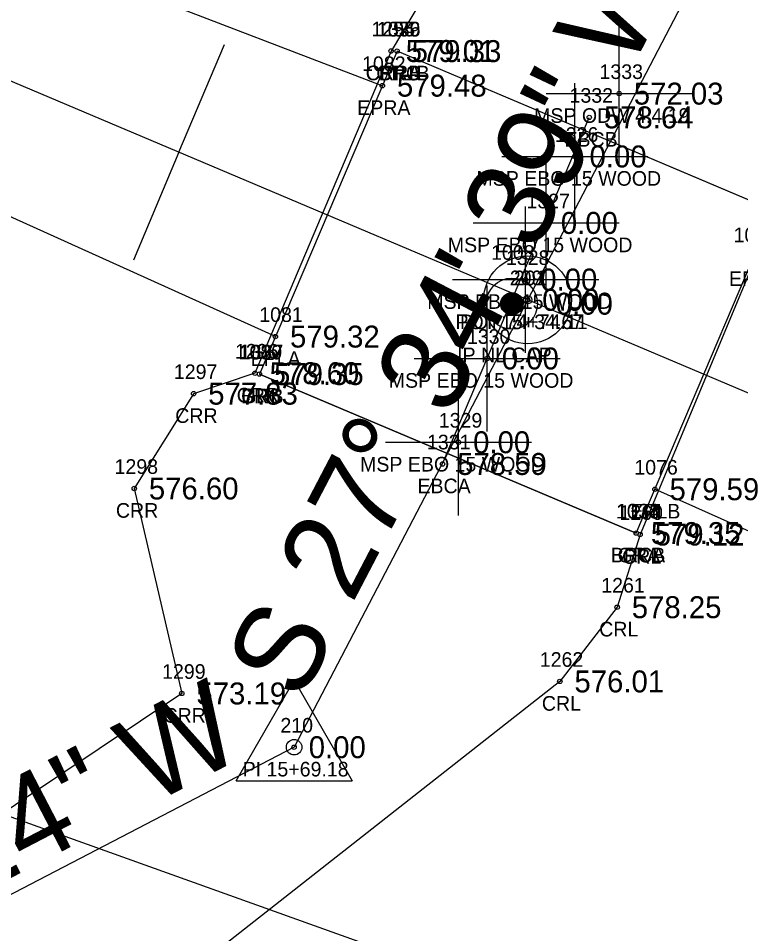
# Model space of a CAD drawing. Extents: x 1664393 to 1667175, y 987029 to 988607.
# Drawn here: x 1665481.2 to 1665530.6, y 987718.5 to 987781.1 of the extents above; entities that cross this region are included whole.
import ezdxf

# ---------------------------------------------------------------- set-up
doc = ezdxf.new("R2010")
doc.units = 0
for name, color, linetype in [('RD_EX_Bridge', 7, 'Continuous'), ('RD_EX_Bridge_txCode', 7, 'Continuous'), ('RD_EX_DV_Prop_txCode', 7, 'Continuous'), ('RD_EX_DV_PropPin', 7, 'Continuous'), ('RD_EX_GuardRail', 7, 'Continuous'), ('RD_EX_GuardRail_txCode', 7, 'Continuous'), ('RD_EX_H2O', 7, 'Continuous'), ('RD_EX_H2O_txCode', 7, 'Continuous'), ('RD_EX_Road', 7, 'Continuous'), ('RD_EX_Road_txCode', 7, 'Continuous'), ('RD_EX_TX_Bridge_ELEV', 7, 'Continuous'), ('RD_EX_TX_DV_Prop_ELEV', 7, 'Continuous'), ('RD_EX_TX_GuardRail_ELEV', 7, 'Continuous'), ('RD_EX_TX_H2O_ELEV', 7, 'Continuous'), ('RD_EX_TX_Misc_ELEV', 7, 'Continuous'), ('RD_EX_TX_Road_ELEV', 7, 'Continuous'), ('RD_EX_VEG', 7, 'Continuous'), ('RD_HC_Cl', 7, 'Continuous'), ('RD_HC_Data', 7, 'Continuous'), ('RD_HC_Data_Tic', 7, 'Continuous'), ('RD_HC_Survey_ELEV', 7, 'Continuous'), ('RD_HC_txCode', 7, 'Continuous'), ('RD_SMD_Locator', 7, 'Continuous')]:
    doc.layers.add(name, color=color, linetype=linetype)

msp = doc.modelspace()

# ---------------------------------------------------------------- linework, layer by layer
at = {"layer": 'RD_EX_Bridge'}
for p, q in [((1665519.233, 987766.682), (1665519.233, 987776.682)), ((1665510.179, 987750.658), (1665520.213, 987774.354)), ((1665517.271, 987762.137), (1665517.271, 987772.137)), ((1665514.233, 987771.682), (1665524.233, 987771.682)), ((1665515.864, 987758.264), (1665515.864, 987768.264)), ((1665512.271, 987767.137), (1665522.271, 987767.137)), ((1665510.864, 987763.264), (1665520.864, 987763.264)), ((1665513.234, 987752.871), (1665513.234, 987762.871)), ((1665508.234, 987757.871), (1665518.234, 987757.871)), ((1665511.271, 987747.143), (1665511.271, 987757.143)), ((1665506.271, 987752.143), (1665516.271, 987752.143))]:
    msp.add_line(p, q, dxfattribs=at)
msp.add_lwpolyline([(1665523.429, 987745.932), (1665532.82, 987767.978), (1665507.067, 987778.884), (1665497.653, 987756.806), (1665523.429, 987745.932)], dxfattribs=at)
for centre in [(1665519.233, 987771.682), (1665517.271, 987767.137), (1665515.864, 987763.264), (1665513.234, 987757.871), (1665511.271, 987752.143)]:
    msp.add_circle(centre, 0.15, dxfattribs=at)
at = {"layer": 'RD_EX_DV_PropPin'}
for p, q in [((1665514.292, 987761.19), (1665514.292, 987762.043)), ((1665514.327, 987761.142), (1665514.327, 987762.09)), ((1665514.362, 987761.101), (1665514.362, 987762.131)), ((1665514.397, 987761.065), (1665514.397, 987762.167)), ((1665514.432, 987761.034), (1665514.432, 987762.198)), ((1665514.467, 987761.006), (1665514.467, 987762.226)), ((1665514.502, 987760.982), (1665514.502, 987762.251)), ((1665514.537, 987760.96), (1665514.537, 987762.273)), ((1665514.572, 987760.941), (1665514.572, 987762.292)), ((1665514.607, 987760.923), (1665514.607, 987762.309)), ((1665514.642, 987760.909), (1665514.642, 987762.324)), ((1665514.677, 987760.896), (1665514.677, 987762.337)), ((1665514.712, 987760.885), (1665514.712, 987762.348)), ((1665514.748, 987760.876), (1665514.748, 987762.357)), ((1665514.783, 987760.868), (1665514.783, 987762.364)), ((1665514.818, 987760.862), (1665514.818, 987762.37)), ((1665514.853, 987760.858), (1665514.853, 987762.374)), ((1665514.888, 987760.856), (1665514.888, 987762.376)), ((1665514.923, 987760.855), (1665514.923, 987762.377)), ((1665514.958, 987760.856), (1665514.958, 987762.376)), ((1665514.993, 987760.858), (1665514.993, 987762.374)), ((1665515.028, 987760.862), (1665515.028, 987762.37)), ((1665515.063, 987760.868), (1665515.063, 987762.364)), ((1665515.098, 987760.876), (1665515.098, 987762.357)), ((1665515.133, 987760.885), (1665515.133, 987762.348)), ((1665515.168, 987760.896), (1665515.168, 987762.337)), ((1665515.203, 987760.909), (1665515.203, 987762.324)), ((1665515.238, 987760.923), (1665515.238, 987762.309)), ((1665515.273, 987760.941), (1665515.273, 987762.292)), ((1665515.308, 987760.96), (1665515.308, 987762.273)), ((1665515.343, 987760.982), (1665515.343, 987762.251)), ((1665515.378, 987761.006), (1665515.378, 987762.226)), ((1665515.413, 987761.034), (1665515.413, 987762.198)), ((1665515.448, 987761.065), (1665515.448, 987762.167)), ((1665515.483, 987761.101), (1665515.483, 987762.131)), ((1665515.518, 987761.142), (1665515.518, 987762.09)), ((1665515.553, 987761.19), (1665515.553, 987762.043)), ((1665514.187, 987761.42), (1665514.187, 987761.812)), ((1665514.222, 987761.318), (1665514.222, 987761.914)), ((1665514.257, 987761.247), (1665514.257, 987761.986)), ((1665515.588, 987761.247), (1665515.588, 987761.986)), ((1665515.623, 987761.318), (1665515.623, 987761.914)), ((1665515.658, 987761.42), (1665515.658, 987761.812))]:
    msp.add_line(p, q, dxfattribs=at)
for radius in [1.75, 0.761]:
    msp.add_circle((1665514.923, 987761.616), radius, dxfattribs=at)
at = {"layer": 'RD_EX_GuardRail'}
for p, q in [((1665532.82, 987767.978), (1665507.067, 987778.884)), ((1665523.429, 987745.932), (1665497.653, 987756.806))]:
    msp.add_line(p, q, dxfattribs=at)
at = {"layer": 'RD_EX_H2O'}
for p, q in [((1665510.35, 987785.057), (1665506.659, 987778.891)), ((1665522.262, 987770.978), (1665522.262, 987780.978)), ((1665517.262, 987775.978), (1665527.262, 987775.978))]:
    msp.add_line(p, q, dxfattribs=at)
for points in [[(1665565.694, 987792.782), (1665555.482, 987787.59), (1665542.576, 987772.172), (1665532.862, 987767.806), (1665532.862, 987767.806), (1665523.69, 987745.834), (1665522.123, 987740.867), (1665518.202, 987735.792), (1665482.823, 987707.998), (1665483.869, 987700.867), (1665513.494, 987706.089), (1665528.039, 987685.521), (1665561.972, 987665.976), (1665593.475, 987679.218), (1665619.367, 987685.12), (1665642.781, 987680.312), (1665663.972, 987651.849), (1665686.025, 987634.258), (1665705.625, 987627.984), (1665724.83, 987594.973)], [(1665506.659, 987778.891), (1665497.349, 987756.863), (1665493.147, 987755.465), (1665489.09, 987748.984), (1665492.342, 987734.97), (1665472.457, 987721.678), (1665444.705, 987712.07), (1665426.388, 987705.523), (1665387.142, 987692.073), (1665353.811, 987678.169), (1665328.18, 987659.888), (1665283.875, 987652.208), (1665224.392, 987676.289), (1665206.474, 987666.979), (1665167.328, 987633.903), (1665123.228, 987629.541), (1665093.052, 987625.537), (1665046.907, 987607.08)]]:
    msp.add_lwpolyline(points, dxfattribs=at)
msp.add_circle((1665522.262, 987775.978), 0.15, dxfattribs=at)
at = {"layer": 'RD_EX_Road'}
for points in [[(1665506.06, 987776.522), (1665471.951, 987789.573), (1665426.522, 987809.188), (1665380.334, 987828.776), (1665335.608, 987847.528), (1665288.25, 987866.825), (1665242.335, 987886.564), (1665197.072, 987906.161), (1665152.201, 987925.426), (1665127.55, 987936.697), (1665104.502, 987945.201), (1665059.192, 987965.303), (1665013.627, 987984.661), (1664966.375, 988005.065), (1664921.664, 988023.835), (1664875.548, 988043.801)], [(1665498.746, 987759.368), (1665465.875, 987774.203), (1665419.779, 987793.882), (1665373.623, 987813.14), (1665327.947, 987832.311), (1665281.425, 987852.296), (1665236.128, 987871.343), (1665189.603, 987890.715), (1665143.921, 987909.971), (1665117.427, 987920.989), (1665086.217, 987934.267), (1665051.623, 987948.552), (1665005.385, 987968.44), (1664960.172, 987987.671), (1664913.527, 988007.622), (1664868.206, 988026.815)], [(1666156.674, 987480.61), (1666109.284, 987500.741), (1666063.55, 987520.043), (1666017.041, 987539.822), (1665971.114, 987559.142), (1665924.884, 987578.792), (1665879.498, 987597.891), (1665833.217, 987617.382), (1665786.906, 987636.812), (1665741.438, 987656.129), (1665695.815, 987675.204), (1665649.264, 987694.848), (1665603.559, 987714.712), (1665558.4, 987733.869), (1665524.706, 987748.932)]]:
    msp.add_lwpolyline(points, dxfattribs=at)
at = {"layer": 'RD_EX_VEG'}
msp.add_lwpolyline([(1666150.204, 987465.221), (1665963.159, 987547.122), (1665727.121, 987646.514), (1665543.179, 987704.13), (1665449.914, 987737.525), (1665163.848, 987870.347), (1665156.075, 987854.029)], dxfattribs=at)
at = {"layer": 'RD_HC_Cl'}
for p, q in [((1666160.052, 987489.414), (1664963.07, 987995.795)), ((1665529.145, 987787.051), (1665500.025, 987731.295)), ((1665500.025, 987731.295), (1665445.607, 987702.995))]:
    msp.add_line(p, q, dxfattribs=at)
at = {"layer": 'RD_HC_Data'}
for p, q in [((1665496.054, 987729.002), (1665500.026, 987735.882)), ((1665500.026, 987735.882), (1665503.995, 987729.002)), ((1665496.054, 987729.002), (1665503.995, 987729.002))]:
    msp.add_line(p, q, dxfattribs=at)
for centre, radius in [((1665515.999, 987761.879), 3), ((1665515.999, 987761.879), 3), ((1665515.999, 987761.879), 0.282), ((1665515.999, 987761.879), 0.282), ((1665500.025, 987731.295), 0.529)]:
    msp.add_circle(centre, radius, dxfattribs=at)
at = {"layer": 'RD_HC_Data_Tic'}
for q in [(1665495.267, 987779.336), (1665489.033, 987764.6)]:
    msp.add_line((1665492.15, 987771.968), q, dxfattribs=at)
at = {"layer": 'RD_SMD_Locator'}
for centre in [(1665506.659, 987778.891), (1665506.659, 987778.891), (1665507.067, 987778.884), (1665507.067, 987778.884), (1665506.06, 987776.522), (1665520.213, 987774.354), (1665515.999, 987761.879), (1665515.999, 987761.879), (1665514.923, 987761.616), (1665498.746, 987759.368), (1665497.349, 987756.863), (1665497.653, 987756.806), (1665497.653, 987756.806), (1665493.147, 987755.465), (1665510.179, 987750.658), (1665489.09, 987748.984), (1665524.706, 987748.932), (1665523.429, 987745.932), (1665523.429, 987745.932), (1665523.429, 987745.932), (1665523.69, 987745.834), (1665522.123, 987740.867), (1665518.202, 987735.792), (1665492.342, 987734.97), (1665500.025, 987731.295)]:
    msp.add_circle(centre, 0.15, dxfattribs=at)

# ---------------------------------------------------------------- texts
at = {"layer": 'RD_EX_Bridge_txCode'}
for s, p in [('1336', (1665505.697, 987779.884)), ('BRC', (1665505.815, 987776.884)), ('1332', (1665518.867, 987775.354)), ('1326', (1665517.863, 987772.682)), ('EBCB', (1665518.513, 987772.354)), ('MSP EBO 15 WOOD', (1665512.5, 987769.682)), ('1327', (1665515.924, 987768.137)), ('MSP EBO 15 WOOD', (1665510.539, 987765.137)), ('1328', (1665514.518, 987764.264)), ('MSP EBO 15 WOOD', (1665509.132, 987761.264)), ('1330', (1665511.848, 987758.871)), ('1337', (1665496.307, 987757.806)), ('MSP EBO 15 WOOD', (1665506.501, 987755.871)), ('BRC', (1665496.401, 987754.806)), ('1329', (1665509.924, 987753.143)), ('1331', (1665509.116, 987751.658)), ('MSP EBO 15 WOOD', (1665504.538, 987750.143)), ('EBCA', (1665508.462, 987748.658)), ('1334', (1665522.082, 987746.932)), ('1338', (1665522.082, 987746.932)), ('BRCA', (1665521.688, 987743.932)), ('BRCB', (1665521.704, 987743.932))]:
    msp.add_text(s, height=1, dxfattribs=at).set_placement(p)
at = {"layer": 'RD_EX_DV_Prop_txCode'}
for s, p in [('1008', (1665513.497, 987764.616)), ('IP NL CAP', (1665511.175, 987757.616))]:
    msp.add_text(s, height=1, dxfattribs=at).set_placement(p)
at = {"layer": 'RD_EX_GuardRail_txCode'}
for s, p in [('1079', (1665505.681, 987779.884)), ('GR1B', (1665505.65, 987776.884)), ('1080', (1665496.228, 987757.806)), ('GRB', (1665496.401, 987754.806)), ('1077', (1665522.043, 987746.932)), ('GRA', (1665522.161, 987743.932))]:
    msp.add_text(s, height=1, dxfattribs=at).set_placement(p)
at = {"layer": 'RD_EX_H2O_txCode'}
for s, p in [('1254', (1665505.313, 987779.891)), ('1295', (1665505.313, 987779.891)), ('CRRA', (1665504.919, 987776.891)), ('CRRB', (1665504.935, 987776.891)), ('1333', (1665520.916, 987776.978)), ('MSP ODW 4.4.19', (1665516.443, 987773.978)), ('1296', (1665495.979, 987757.863)), ('1297', (1665491.801, 987756.465)), ('CRR', (1665496.097, 987754.863)), ('CRR', (1665491.895, 987753.465)), ('1298', (1665487.744, 987749.984)), ('CRR', (1665487.838, 987746.984)), ('1260', (1665522.28, 987746.834)), ('CRL', (1665522.461, 987743.834)), ('1261', (1665521.037, 987741.867)), ('CRL', (1665520.895, 987738.867)), ('1262', (1665516.832, 987736.792)), ('1299', (1665490.996, 987735.97)), ('CRL', (1665516.974, 987733.792)), ('CRR', (1665491.09, 987732.97))]:
    msp.add_text(s, height=1, dxfattribs=at).set_placement(p)
at = {"layer": 'RD_EX_Road_txCode'}
for s, p in [('1082', (1665504.674, 987777.522)), ('EPRA', (1665504.343, 987774.522)), ('1075', (1665530.089, 987765.82)), ('EPRB', (1665529.774, 987762.82)), ('1081', (1665497.643, 987760.368)), ('EPLA', (1665497.053, 987757.368)), ('1076', (1665523.297, 987749.932)), ('EPLB', (1665523.029, 987746.932))]:
    msp.add_text(s, height=1, dxfattribs=at).set_placement(p)
at = {"layer": 'RD_EX_TX_Bridge_ELEV'}
for s, p in [('579.33', (1665508.067, 987778.134)), ('578.64', (1665521.213, 987773.604)), ('579.35', (1665498.653, 987756.056)), ('578.59', (1665511.179, 987749.908)), ('579.35', (1665524.429, 987745.182)), ('579.35', (1665524.429, 987745.182))]:
    msp.add_text(s, height=1.5, dxfattribs=at).set_placement(p)
at = {"layer": 'RD_EX_TX_DV_Prop_ELEV'}
msp.add_text('0.00', height=1.5, dxfattribs=at).set_placement((1665517.923, 987760.866))
at = {"layer": 'RD_EX_TX_GuardRail_ELEV'}
for s, p in [('579.33', (1665508.067, 987778.134)), ('579.35', (1665498.653, 987756.056)), ('579.35', (1665524.429, 987745.182))]:
    msp.add_text(s, height=1.5, dxfattribs=at).set_placement(p)
at = {"layer": 'RD_EX_TX_H2O_ELEV'}
for s, p in [('579.01', (1665507.659, 987778.141)), ('579.01', (1665507.659, 987778.141)), ('578.60', (1665498.349, 987756.113)), ('577.83', (1665494.147, 987754.715)), ('576.60', (1665490.09, 987748.234)), ('579.12', (1665524.69, 987745.084)), ('578.25', (1665523.123, 987740.117)), ('576.01', (1665519.202, 987735.042)), ('573.19', (1665493.342, 987734.22))]:
    msp.add_text(s, height=1.5, dxfattribs=at).set_placement(p)
at = {"layer": 'RD_EX_TX_Misc_ELEV'}
for s, p in [('572.03', (1665523.262, 987775.228)), ('0.00', (1665520.233, 987770.932)), ('0.00', (1665518.271, 987766.387)), ('0.00', (1665516.864, 987762.514)), ('0.00', (1665514.234, 987757.121)), ('0.00', (1665512.271, 987751.393))]:
    msp.add_text(s, height=1.5, dxfattribs=at).set_placement(p)
at = {"layer": 'RD_EX_TX_Road_ELEV'}
for s, p in [('579.48', (1665507.06, 987775.772)), ('579.32', (1665499.746, 987758.618)), ('579.59', (1665525.706, 987748.182))]:
    msp.add_text(s, height=1.5, dxfattribs=at).set_placement(p)
at = {"layer": 'RD_HC_Data'}
for s, rotation, p in [('S 27%%d 34\' 39" W', 62.42242, (1665500.465, 987734.298)), ('S 62%%d 31\' 24" W', 27.47659, (1665446.993, 987704.843))]:
    msp.add_text(s, height=6, rotation=rotation, dxfattribs=at).set_placement(p)
at = {"layer": 'RD_HC_Survey_ELEV'}
for p in [(1665516.999, 987761.129), (1665516.999, 987761.129), (1665501.025, 987730.545)]:
    msp.add_text('0.00', height=1.5, dxfattribs=at).set_placement(p)
at = {"layer": 'RD_HC_txCode'}
for s, p in [('209', (1665514.778, 987762.879)), ('201', (1665515.062, 987762.879)), ('POT 15+34.67', (1665511.062, 987759.879)), ('POT 74+74.11', (1665511.369, 987759.879)), ('210', (1665499.088, 987732.295)), ('PI 15+69.18', (1665496.505, 987729.295))]:
    msp.add_text(s, height=1, dxfattribs=at).set_placement(p)

doc.saveas('drawing.dxf')
